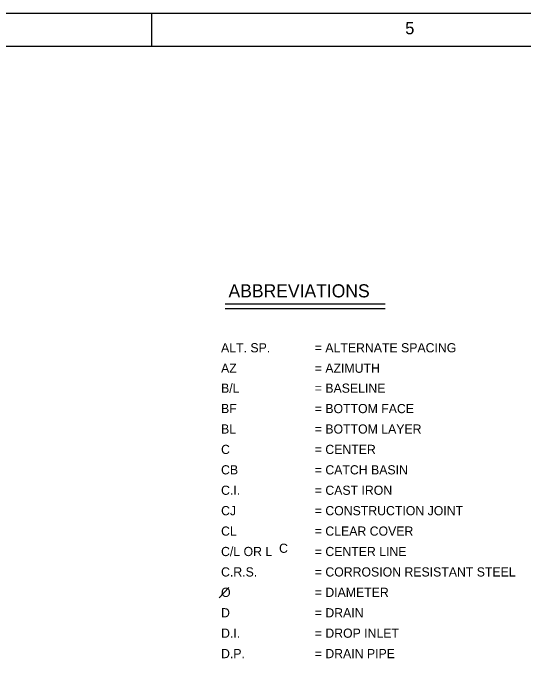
# Model space of a CAD drawing. Extents: x 22369.62 to 22373.29, y 22369.62 to 22372.46.
# Drawn here: x 22372.185 to 22372.836, y 22371.619 to 22372.455 of the extents above; entities that cross this region are included whole.
import ezdxf

# ---------------------------------------------------------------- set-up
doc = ezdxf.new("R2010")
doc.units = 0
for name, color, linetype in [('Level 1', 7, 'Continuous'), ('Level 10', 7, 'Continuous'), ('Level 3', 7, 'Continuous'), ('Level 4', 7, 'Continuous'), ('Level 9', 7, 'Continuous')]:
    doc.layers.add(name, color=color, linetype=linetype)

msp = doc.modelspace()

# ---------------------------------------------------------------- linework, layer by layer
at = {"layer": 'Level 1'}
msp.add_lwpolyline([(22369.6213, 22372.4553), (22373.288, 22372.4553), (22373.288, 22369.6213), (22369.6213, 22369.6213)], close=True, dxfattribs=at)
at = {"layer": 'Level 10'}
for p, q in [((22372.362, 22372.4133), (22372.362, 22372.4553)), ((22372.45573, 22372.08443), (22372.65961, 22372.08443)), ((22372.45573, 22372.07863), (22372.65961, 22372.07863))]:
    msp.add_line(p, q, dxfattribs=at)
at = {"layer": 'Level 4'}
msp.add_line((22372.44777, 22371.70975), (22372.46015, 22371.72261), dxfattribs=at)
at = {"layer": 'Level 9'}
msp.add_line((22369.7463, 22372.4133), (22373.017, 22372.4133), dxfattribs=at)

# ---------------------------------------------------------------- texts
at = {"layer": 'Level 1'}
msp.add_text('5', height=0.01561, dxfattribs=at).set_placement((22372.685, 22372.4283))
at = {"layer": 'Level 3'}
msp.add_text('ABBREVIATIONS', height=0.0166979, dxfattribs=at).set_placement((22372.45978, 22372.09275))
at = {"layer": 'Level 4'}
for s, height, p in [('ALT. SP.', 0.011698, (22372.4503, 22372.02265)), ('= ALTERNATE SPACING', 0.0116979, (22372.56972, 22372.02265)), ('AZ', 0.011698, (22372.4503, 22371.99661)), ('= AZIMUTH', 0.011698, (22372.56972, 22371.99661)), ('B/L', 0.011698, (22372.4503, 22371.97114)), ('= BASELINE', 0.011698, (22372.56972, 22371.97114)), ('BF', 0.011698, (22372.4503, 22371.9451)), ('= BOTTOM FACE', 0.0116979, (22372.56972, 22371.9451)), ('BL', 0.011698, (22372.4503, 22371.91906)), ('= BOTTOM LAYER', 0.0116979, (22372.56972, 22371.91906)), ('C', 0.0117, (22372.4503, 22371.89302)), ('= CENTER', 0.011698, (22372.56972, 22371.89302)), ('CB', 0.011698, (22372.4503, 22371.86698)), ('= CATCH BASIN', 0.0116979, (22372.56972, 22371.86698)), ('C.I.', 0.011698, (22372.4503, 22371.84094)), ('= CAST IRON', 0.0116979, (22372.56972, 22371.84094)), ('CJ', 0.011698, (22372.4503, 22371.81489)), ('= CONSTRUCTION JOINT', 0.0116979, (22372.56972, 22371.81489)), ('CL', 0.011698, (22372.4503, 22371.78885)), ('= CLEAR COVER', 0.0116979, (22372.56972, 22371.78885)), ('C/L OR L', 0.011698, (22372.4503, 22371.76281)), ('C', 0.0117, (22372.52421, 22371.76696)), ('= CENTER LINE', 0.0116979, (22372.56972, 22371.76281)), ('C.R.S.', 0.011698, (22372.4503, 22371.73677)), ('= CORROSION RESISTANT STEEL', 0.0116979, (22372.56972, 22371.73677)), ('O ', 0.011698, (22372.4503, 22371.71073)), ('= DIAMETER', 0.011698, (22372.56972, 22371.71073)), ('D', 0.0117, (22372.4503, 22371.68469)), ('= DRAIN', 0.011698, (22372.56972, 22371.68469)), ('D.I. ', 0.011698, (22372.4503, 22371.65864)), ('= DROP INLET', 0.0116979, (22372.56972, 22371.65864)), ('D.P.', 0.011698, (22372.4503, 22371.6326)), ('= DRAIN PIPE', 0.0116979, (22372.56972, 22371.6326))]:
    msp.add_text(s, height=height, dxfattribs=at).set_placement(p)

doc.saveas('drawing.dxf')
